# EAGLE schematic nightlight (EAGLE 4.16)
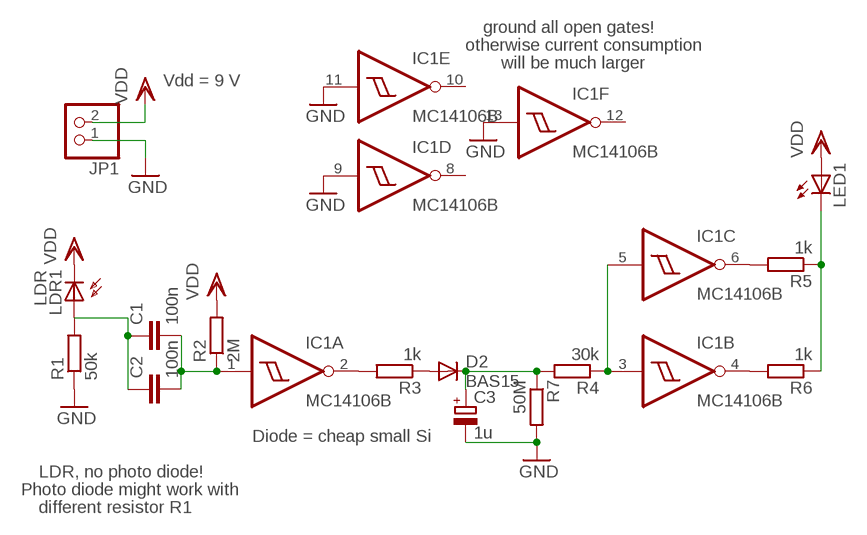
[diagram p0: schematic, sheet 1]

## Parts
C1  100n  C-EU025-025X050  [C025-025X050]
C2  100n  C-EU025-025X050  [C025-025X050]
C3  1u  CPOL-EUE2.5-5  [E2,5-5]
D2  BAS15  [DO34-7]
IC1  MC14106B  40106N  [DIL14]
JP1  PINHD-1X2  [1X02]
LDR1  LDR  SFH225  [SFH225]
LED1  LED5MM  [LED5MM]
R1  50k  R-EU_0204/7  [0204/7]
R2  2M  R-EU_0204/7  [0204/7]
R3  1k  R-EU_0204/7  [0204/7]
R4  30k  R-EU_0204/7  [0204/7]
R5  1k  R-EU_0204/7  [0204/7]
R6  1k  R-EU_0204/7  [0204/7]
R7  50M  R-EU_0204/7  [0204/7]

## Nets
GND: C3.- IC1.9(D:I) IC1.11(E:I) IC1.13(F:I) JP1.1 R1.1 R7.2
N$2: C1.2 C2.2 IC1.1(A:I) R2.1
N$3: IC1.2(A:O) R3.2
N$4: IC1.3(B:I) IC1.5(C:I) R4.1
N$5: IC1.6(C:O) R5.2
N$6: IC1.4(B:O) R6.2
N$7: C3.+ D2.C R4.2 R7.1
N$8: D2.A R3.1
N$9: C1.1 C2.1 LDR1.A R1.2
N$10: LED1.K(C) R5.1 R6.1
VDD: JP1.2 LDR1.K(C) LED1.A R2.2
Unconnected: IC1.8(D:O) IC1.10(E:O) IC1.12(F:O)

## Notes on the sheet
- ground all open gates!
- otherwise current consumption
- will be much larger
- Vdd = 9 V
- Diode = cheap small Si
- LDR, no photo diode!
- Photo diode might work with
- different resistor R1

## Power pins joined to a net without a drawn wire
VDD: IC1.14(P:VDD)
VSS: IC1.7(P:VSS)

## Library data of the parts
C1 C2 = rcl:C-EU: CAPACITOR, European symbol
C3 = rcl:CPOL-EU: POLARIZED CAPACITOR, European symbol
D2 = diode:BAS15: DIODE
IC1 = 40xx:40106: Hex SCHMITT TRIGGER
JP1 = pinhead:PINHD-1X2: PIN HEADER
LDR1 = opto-trans-siemens:SFH225: PHOTO DIODE
LED1 = led:LED: LED
R1-R7 = rcl:R-EU_: RESISTOR, European symbol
